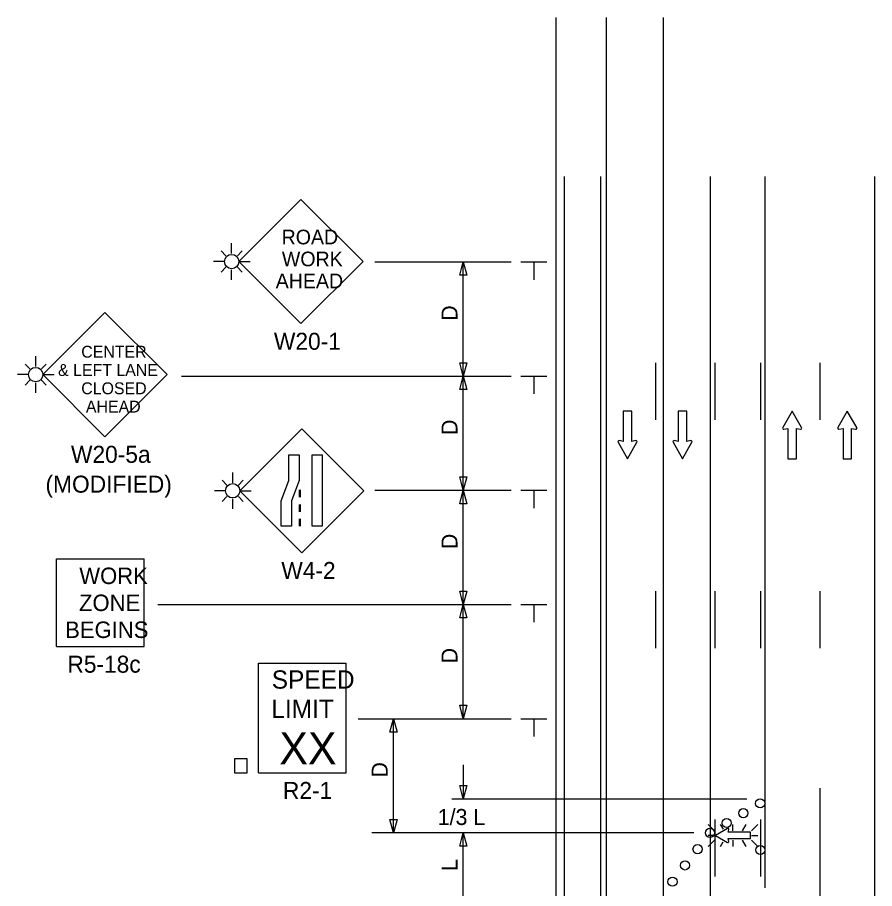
# Model space of a CAD drawing. Extents: x 16752 to 18475, y 7011 to 8262.
# Drawn here: x 16752.3 to 17127.7, y 7880.9 to 8262.3 of the extents above; entities that cross this region are included whole.
import ezdxf

# ---------------------------------------------------------------- set-up
doc = ezdxf.new("R2010")
doc.units = 0
for name, color, linetype in [('ALI_LEGAL_EX', 7, 'Continuous'), ('MT_SCRATCH_LEVEL_E', 7, 'Continuous'), ('PAVT_EDGE_EX', 7, 'Continuous'), ('TRAFFIC_SIGNS_PR', 7, 'Continuous'), ('TYPICAL_TEXT_DIMEN_PR', 7, 'Continuous')]:
    doc.layers.add(name, color=color, linetype=linetype)

msp = doc.modelspace()

# ---------------------------------------------------------------- linework, layer by layer
at = {"layer": 'ALI_LEGAL_EX'}
for points in [[(17031.71, 8111.16), (17031.71, 8086.16)], [(17031.71, 8111.16), (17031.71, 8086.16)], [(17057.71, 8111.16), (17057.71, 8086.16)], [(17057.71, 8111.16), (17057.71, 8086.16)], [(17077.71, 8111.16), (17077.71, 8086.16)], [(17077.71, 8111.16), (17077.71, 8086.16)], [(17103.71, 8111.16), (17103.71, 8086.16)], [(17103.71, 8111.16), (17103.71, 8086.16)], [(17031.71, 8011.16), (17031.71, 7986.16)], [(17031.71, 8011.16), (17031.71, 7986.16)], [(17057.71, 8011.16), (17057.71, 7986.16)], [(17057.71, 8011.16), (17057.71, 7986.16)], [(17077.71, 8011.16), (17077.71, 7986.16)], [(17077.71, 8011.16), (17077.71, 7986.16)], [(17103.71, 8011.16), (17103.71, 7986.16)], [(17103.71, 8011.16), (17103.71, 7986.16)], [(17057.71, 7911.16), (17057.71, 7886.16)], [(17057.71, 7911.16), (17057.71, 7886.16)], [(17077.71, 7911.16), (17077.71, 7886.16)], [(17077.71, 7911.16), (17077.71, 7886.16)], [(17103.71, 7911.16), (17103.71, 7886.16)]]:
    msp.add_lwpolyline(points, dxfattribs=at)
at = {"layer": 'MT_SCRATCH_LEVEL_E'}
for p, q in [((17021.38, 8089.95), (17017.64, 8089.95)), ((17017.64, 8089.95), (17017.64, 8076.7)), ((17021.38, 8089.95), (17017.64, 8089.95)), ((17017.64, 8089.95), (17017.64, 8076.7)), ((17021.38, 8089.95), (17017.64, 8089.95)), ((17017.64, 8089.95), (17017.64, 8076.7)), ((17021.38, 8089.95), (17017.64, 8089.95)), ((17017.64, 8089.95), (17017.64, 8076.7)), ((17021.38, 8076.7), (17021.38, 8089.95)), ((17021.38, 8076.7), (17021.38, 8089.95)), ((17021.38, 8076.7), (17021.38, 8089.95)), ((17021.38, 8076.7), (17021.38, 8089.95)), ((17045.45, 8089.95), (17041.71, 8089.95)), ((17041.71, 8089.95), (17041.71, 8076.7)), ((17045.45, 8089.95), (17041.71, 8089.95)), ((17041.71, 8089.95), (17041.71, 8076.7)), ((17045.45, 8089.95), (17041.71, 8089.95)), ((17041.71, 8089.95), (17041.71, 8076.7)), ((17045.45, 8089.95), (17041.71, 8089.95)), ((17041.71, 8089.95), (17041.71, 8076.7)), ((17045.45, 8076.7), (17045.45, 8089.95)), ((17045.45, 8076.7), (17045.45, 8089.95)), ((17045.45, 8076.7), (17045.45, 8089.95)), ((17045.45, 8076.7), (17045.45, 8089.95)), ((17091.58, 8089.95), (17087.47, 8082.71)), ((17091.58, 8089.95), (17087.47, 8082.71)), ((17095.73, 8082.71), (17091.58, 8089.95)), ((17095.73, 8082.71), (17091.58, 8089.95)), ((17115.75, 8089.95), (17111.64, 8082.71)), ((17115.75, 8089.95), (17111.64, 8082.71)), ((17119.9, 8082.71), (17115.75, 8089.95)), ((17119.9, 8082.71), (17115.75, 8089.95)), ((17087.95, 8082.03), (17089.73, 8082.34)), ((17087.95, 8082.03), (17089.73, 8082.34)), ((17089.73, 8082.34), (17089.73, 8069.09)), ((17089.73, 8082.34), (17089.73, 8069.09)), ((17093.47, 8069.09), (17093.47, 8082.34)), ((17093.47, 8082.34), (17095.25, 8082.03)), ((17093.47, 8069.09), (17093.47, 8082.34)), ((17093.47, 8082.34), (17095.25, 8082.03)), ((17112.12, 8082.03), (17113.9, 8082.34)), ((17112.12, 8082.03), (17113.9, 8082.34)), ((17113.9, 8082.34), (17113.9, 8069.09)), ((17113.9, 8082.34), (17113.9, 8069.09)), ((17117.64, 8069.09), (17117.64, 8082.34)), ((17117.64, 8082.34), (17119.42, 8082.03)), ((17117.64, 8069.09), (17117.64, 8082.34)), ((17117.64, 8082.34), (17119.42, 8082.03)), ((17015.38, 8076.33), (17019.53, 8069.09)), ((17015.38, 8076.33), (17019.53, 8069.09)), ((17015.38, 8076.33), (17019.53, 8069.09)), ((17015.38, 8076.33), (17019.53, 8069.09)), ((17017.64, 8076.7), (17015.86, 8077.01)), ((17017.64, 8076.7), (17015.86, 8077.01)), ((17017.64, 8076.7), (17015.86, 8077.01)), ((17017.64, 8076.7), (17015.86, 8077.01)), ((17019.53, 8069.09), (17023.64, 8076.33)), ((17019.53, 8069.09), (17023.64, 8076.33)), ((17019.53, 8069.09), (17023.64, 8076.33)), ((17019.53, 8069.09), (17023.64, 8076.33)), ((17023.16, 8077.01), (17021.38, 8076.7)), ((17023.16, 8077.01), (17021.38, 8076.7)), ((17023.16, 8077.01), (17021.38, 8076.7)), ((17023.16, 8077.01), (17021.38, 8076.7)), ((17039.45, 8076.33), (17043.6, 8069.09)), ((17039.45, 8076.33), (17043.6, 8069.09)), ((17039.45, 8076.33), (17043.6, 8069.09)), ((17039.45, 8076.33), (17043.6, 8069.09)), ((17041.71, 8076.7), (17039.93, 8077.01)), ((17041.71, 8076.7), (17039.93, 8077.01)), ((17041.71, 8076.7), (17039.93, 8077.01)), ((17041.71, 8076.7), (17039.93, 8077.01)), ((17043.6, 8069.09), (17047.71, 8076.33)), ((17043.6, 8069.09), (17047.71, 8076.33)), ((17043.6, 8069.09), (17047.71, 8076.33)), ((17043.6, 8069.09), (17047.71, 8076.33)), ((17047.23, 8077.01), (17045.45, 8076.7)), ((17047.23, 8077.01), (17045.45, 8076.7)), ((17047.23, 8077.01), (17045.45, 8076.7)), ((17047.23, 8077.01), (17045.45, 8076.7)), ((17089.73, 8069.09), (17093.47, 8069.09)), ((17089.73, 8069.09), (17093.47, 8069.09)), ((17113.9, 8069.09), (17117.64, 8069.09)), ((17113.9, 8069.09), (17117.64, 8069.09))]:
    msp.add_line(p, q, dxfattribs=at)
for centre, start, end in [((17087.88, 8082.49), 150.4248, 279.9638), ((17087.88, 8082.49), 150.4248, 279.9638), ((17095.32, 8082.49), 260.0362, 29.7731), ((17095.32, 8082.49), 260.0362, 29.7731), ((17112.05, 8082.49), 150.4248, 279.9638), ((17112.05, 8082.49), 150.4248, 279.9638), ((17119.49, 8082.49), 260.0362, 29.7731), ((17119.49, 8082.49), 260.0362, 29.7731), ((17015.79, 8076.55), 80.0362, 209.7731), ((17015.79, 8076.55), 80.0362, 209.7731), ((17015.79, 8076.55), 80.0362, 209.7731), ((17015.79, 8076.55), 80.0362, 209.7731), ((17023.23, 8076.55), 330.4248, 99.9638), ((17023.23, 8076.55), 330.4248, 99.9638), ((17023.23, 8076.55), 330.4248, 99.9638), ((17023.23, 8076.55), 330.4248, 99.9638), ((17039.86, 8076.55), 80.0362, 209.7731), ((17039.86, 8076.55), 80.0362, 209.7731), ((17039.86, 8076.55), 80.0362, 209.7731), ((17039.86, 8076.55), 80.0362, 209.7731), ((17047.3, 8076.55), 330.4248, 99.9638), ((17047.3, 8076.55), 330.4248, 99.9638), ((17047.3, 8076.55), 330.4248, 99.9638), ((17047.3, 8076.55), 330.4248, 99.9638)]:
    msp.add_arc(centre, 0.463, start, end, dxfattribs=at)
at = {"layer": 'PAVT_EDGE_EX'}
for p, q in [((16988.15, 8262.34), (16988.15, 7433.15)), ((17010.15, 8262.34), (17010.15, 7433.15)), ((17035.15, 8262.34), (17035.15, 7433.15)), ((16991.71, 8192.65), (16991.71, 7386.98)), ((17007.71, 8192.65), (17007.71, 7386.98)), ((17055.71, 8192.65), (17055.71, 7852.65)), ((17055.71, 8192.65), (17055.71, 7851.93)), ((17079.71, 8192.65), (17079.71, 7881.16)), ((17079.71, 8192.65), (17079.71, 7882.21)), ((17127.71, 8192.65), (17127.71, 7386.98)), ((17103.71, 7924.78), (17103.71, 7869.32))]:
    msp.add_line(p, q, dxfattribs=at)
at = {"layer": 'TRAFFIC_SIGNS_PR'}
for p, q in [((16876.5, 8182.62), (16849.32, 8155.44)), ((16903.69, 8155.44), (16876.5, 8182.62)), ((16846.16, 8158.99), (16846.16, 8163.49)), ((16843.65, 8157.95), (16841.54, 8160.06)), ((16848.68, 8157.95), (16850.78, 8160.06)), ((16843.01, 8155.44), (16838.17, 8155.44)), ((16843.65, 8152.92), (16841.54, 8150.81)), ((16846.16, 8147.47), (16846.16, 8151.88)), ((16848.68, 8152.92), (16850.78, 8150.82)), ((16849.32, 8155.44), (16876.5, 8128.25)), ((16849.32, 8155.44), (16854.2, 8155.44)), ((16876.5, 8128.25), (16903.69, 8155.44)), ((16790.67, 8133.12), (16763.48, 8105.94)), ((16817.85, 8105.94), (16790.67, 8133.12)), ((16760.33, 8109.49), (16760.33, 8113.99)), ((16757.81, 8108.45), (16755.71, 8110.56)), ((16762.84, 8108.45), (16764.95, 8110.56)), ((16757.17, 8105.94), (16752.33, 8105.94)), ((16757.81, 8103.43), (16755.71, 8101.32)), ((16760.33, 8097.97), (16760.33, 8102.38)), ((16762.84, 8103.43), (16764.95, 8101.32)), ((16763.48, 8105.94), (16790.67, 8078.75)), ((16763.48, 8105.94), (16768.36, 8105.94)), ((16763.48, 8105.94), (16790.67, 8078.75)), ((16790.67, 8078.75), (16817.85, 8105.94)), ((16876.95, 8082.17), (16849.8, 8055.02)), ((16904.1, 8055.02), (16876.95, 8082.17)), ((16846.61, 8058.61), (16846.61, 8063.11)), ((16844.1, 8057.57), (16841.99, 8059.68)), ((16849.12, 8057.57), (16851.23, 8059.68)), ((16843.46, 8055.06), (16838.62, 8055.06)), ((16849.76, 8055.06), (16854.65, 8055.06)), ((16849.8, 8055.02), (16876.95, 8027.87)), ((16875.7, 8055.51), (16875.7, 8052.31)), ((16876.1, 8055.51), (16876.1, 8052.31)), ((16876.95, 8027.87), (16904.1, 8055.02)), ((16844.1, 8052.54), (16841.99, 8050.43)), ((16846.61, 8047.09), (16846.61, 8051.5)), ((16849.12, 8052.54), (16851.23, 8050.44)), ((16875.7, 8049.11), (16875.7, 8045.91)), ((16876.1, 8049.11), (16876.1, 8045.91)), ((16875.7, 8042.71), (16875.7, 8039.51)), ((16876.1, 8042.71), (16876.1, 8039.51)), ((16769.43, 7986.85), (16769.43, 8025.25)), ((16769.43, 8025.25), (16807.83, 8025.25)), ((16807.83, 7986.85), (16807.83, 8025.25)), ((16769.43, 7986.85), (16807.83, 7986.85)), ((16857.94, 7979.56), (16896.34, 7979.56)), ((16857.94, 7931.56), (16857.94, 7979.56)), ((16896.34, 7931.56), (16896.34, 7979.56)), ((16857.94, 7931.56), (16896.34, 7931.56)), ((17054.8, 7909), (17057.62, 7906.18)), ((17061.52, 7906.82), (17060.26, 7909)), ((17065.7, 7906.18), (17065.7, 7909)), ((17069.83, 7906.18), (17071.46, 7909)), ((17073.78, 7906.18), (17076.61, 7909)), ((17057.62, 7904.15), (17054.8, 7904.15)), ((17073.78, 7904.15), (17076.61, 7904.15)), ((17054.8, 7899.3), (17057.62, 7902.12)), ((17060.23, 7899.3), (17061.44, 7901.39)), ((17065.7, 7902.12), (17065.7, 7899.3)), ((17071.49, 7899.3), (17069.86, 7902.12)), ((17073.78, 7902.12), (17076.61, 7899.3))]:
    msp.add_line(p, q, dxfattribs=at)
for points in [[(16875.7, 8070.76), (16875.7, 8059.58), (16872.36, 8050.69), (16872.36, 8039.51), (16867.87, 8039.51), (16867.87, 8050.69), (16871.21, 8059.58), (16871.21, 8070.76)], [(16885.84, 8070.76), (16885.84, 8039.51), (16881.35, 8039.51), (16881.35, 8070.76)], [(16847.33, 7931.56), (16852.92, 7931.56), (16852.92, 7937.73), (16847.33, 7937.73)]]:
    msp.add_lwpolyline(points, close=True, dxfattribs=at)
for points in [[(17063.37, 7907.16), (17058.06, 7904.15), (17063.37, 7901.11)], [(17063.87, 7901.47), (17063.64, 7902.76), (17073.37, 7902.76), (17073.37, 7905.51), (17063.64, 7905.51), (17063.88, 7906.81)]]:
    msp.add_lwpolyline(points, dxfattribs=at)
for centre, radius in [((16846.16, 8155.44), 3.15), ((16760.33, 8105.94), 3.15), ((16846.61, 8055.06), 3.15), ((17077.6, 7918.19), 2), ((17070.27, 7913.88), 2), ((17062.94, 7909.57), 2), ((17055.61, 7905.27), 2), ((17050.19, 7898.13), 2), ((17077.65, 7897.79), 2), ((17044.7, 7891.01), 2), ((17039.21, 7883.88), 2)]:
    msp.add_circle(centre, radius, dxfattribs=at)
for centre, start, end in [((17063.54, 7906.87), 350.7308, 118.8916), ((17063.54, 7901.41), 241.4833, 9.9593)]:
    msp.add_arc(centre, 0.341, start, end, dxfattribs=at)
at = {"layer": 'TYPICAL_TEXT_DIMEN_PR'}
for p, q in [((16908.85, 8155.27), (16968.61, 8155.27)), ((16946.04, 8149.41), (16947.61, 8155.27)), ((16946.04, 8149.41), (16947.61, 8155.27)), ((16947.61, 8155.27), (16949.18, 8149.41)), ((16947.61, 8155.27), (16949.18, 8149.41)), ((16947.61, 8105.27), (16947.61, 8155.27)), ((16972.86, 8155.27), (16984.11, 8155.27)), ((16972.86, 8155.27), (16984.11, 8155.27)), ((16978.49, 8155.27), (16978.49, 8147.49)), ((16978.49, 8155.27), (16978.49, 8147.49)), ((16947.61, 8149.41), (16946.04, 8149.41)), ((16947.61, 8149.41), (16946.04, 8149.41)), ((16949.18, 8149.41), (16947.61, 8149.41)), ((16949.18, 8149.41), (16947.61, 8149.41)), ((16947.61, 8105.27), (16946.04, 8111.13)), ((16946.04, 8111.13), (16947.61, 8111.13)), ((16947.61, 8105.27), (16946.04, 8111.13)), ((16946.04, 8111.13), (16947.61, 8111.13)), ((16947.61, 8111.13), (16949.18, 8111.13)), ((16949.18, 8111.13), (16947.61, 8105.27)), ((16947.61, 8111.13), (16949.18, 8111.13)), ((16949.18, 8111.13), (16947.61, 8105.27)), ((16824.2, 8105.27), (16968.61, 8105.27)), ((16946.04, 8099.41), (16947.61, 8105.27)), ((16946.04, 8099.41), (16947.61, 8105.27)), ((16947.61, 8105.27), (16949.18, 8099.41)), ((16947.61, 8055.27), (16947.61, 8105.27)), ((16947.61, 8105.27), (16949.18, 8099.41)), ((16947.61, 8055.27), (16947.61, 8105.27)), ((16972.86, 8105.27), (16984.11, 8105.27)), ((16978.49, 8105.27), (16978.49, 8097.49)), ((16947.61, 8099.41), (16946.04, 8099.41)), ((16947.61, 8099.41), (16946.04, 8099.41)), ((16949.18, 8099.41), (16947.61, 8099.41)), ((16949.18, 8099.41), (16947.61, 8099.41)), ((16947.61, 8055.27), (16946.04, 8061.13)), ((16946.04, 8061.13), (16947.61, 8061.13)), ((16947.61, 8055.27), (16946.04, 8061.13)), ((16946.04, 8061.13), (16947.61, 8061.13)), ((16947.61, 8061.13), (16949.18, 8061.13)), ((16949.18, 8061.13), (16947.61, 8055.27)), ((16947.61, 8061.13), (16949.18, 8061.13)), ((16949.18, 8061.13), (16947.61, 8055.27)), ((16908.85, 8055.27), (16968.61, 8055.27)), ((16946.04, 8049.41), (16947.61, 8055.27)), ((16946.04, 8049.41), (16947.61, 8055.27)), ((16947.61, 8055.27), (16949.18, 8049.41)), ((16947.61, 8055.27), (16949.18, 8049.41)), ((16947.61, 8005.27), (16947.61, 8055.27)), ((16972.86, 8055.27), (16984.11, 8055.27)), ((16972.86, 8055.27), (16984.11, 8055.27)), ((16978.49, 8055.27), (16978.49, 8047.49)), ((16978.49, 8055.27), (16978.49, 8047.49)), ((16947.61, 8049.41), (16946.04, 8049.41)), ((16947.61, 8049.41), (16946.04, 8049.41)), ((16949.18, 8049.41), (16947.61, 8049.41)), ((16949.18, 8049.41), (16947.61, 8049.41)), ((16947.61, 8005.27), (16946.04, 8011.13)), ((16946.04, 8011.13), (16947.61, 8011.13)), ((16947.61, 8005.27), (16946.04, 8011.13)), ((16946.04, 8011.13), (16947.61, 8011.13)), ((16947.61, 8011.13), (16949.18, 8011.13)), ((16949.18, 8011.13), (16947.61, 8005.27)), ((16947.61, 8011.13), (16949.18, 8011.13)), ((16949.18, 8011.13), (16947.61, 8005.27)), ((16813.85, 8005.27), (16968.61, 8005.27)), ((16946.04, 7999.41), (16947.61, 8005.27)), ((16946.04, 7999.41), (16947.61, 8005.27)), ((16947.61, 8005.27), (16949.18, 7999.41)), ((16947.61, 7955.27), (16947.61, 8005.27)), ((16947.61, 8005.27), (16949.18, 7999.41)), ((16947.61, 7955.27), (16947.61, 8005.27)), ((16972.86, 8005.27), (16984.11, 8005.27)), ((16978.49, 8005.27), (16978.49, 7997.49)), ((16947.61, 7999.41), (16946.04, 7999.41)), ((16947.61, 7999.41), (16946.04, 7999.41)), ((16949.18, 7999.41), (16947.61, 7999.41)), ((16949.18, 7999.41), (16947.61, 7999.41)), ((16947.61, 7955.27), (16946.04, 7961.13)), ((16946.04, 7961.13), (16947.61, 7961.13)), ((16947.61, 7955.27), (16946.04, 7961.13)), ((16946.04, 7961.13), (16947.61, 7961.13)), ((16947.61, 7961.13), (16949.18, 7961.13)), ((16949.18, 7961.13), (16947.61, 7955.27)), ((16947.61, 7961.13), (16949.18, 7961.13)), ((16949.18, 7961.13), (16947.61, 7955.27)), ((16901.49, 7955.27), (16968.61, 7955.27)), ((16915.47, 7949.41), (16917.04, 7955.27)), ((16917.04, 7955.27), (16918.61, 7949.41)), ((16917.04, 7905.27), (16917.04, 7955.27)), ((16972.86, 7955.27), (16984.11, 7955.27)), ((16978.49, 7955.27), (16978.49, 7947.49)), ((16917.04, 7949.41), (16915.47, 7949.41)), ((16918.61, 7949.41), (16917.04, 7949.41)), ((16947.61, 7935.11), (16947.61, 7920.19)), ((16947.61, 7920.19), (16946.04, 7926.06)), ((16946.04, 7926.06), (16947.61, 7926.06)), ((16947.61, 7920.19), (16946.04, 7926.06)), ((16946.04, 7926.06), (16947.61, 7926.06)), ((16947.61, 7926.06), (16949.18, 7926.06)), ((16949.18, 7926.06), (16947.61, 7920.19)), ((16947.61, 7926.06), (16949.18, 7926.06)), ((16949.18, 7926.06), (16947.61, 7920.19)), ((16942.61, 7920.19), (17071.75, 7920.19)), ((16917.04, 7905.27), (16915.47, 7911.13)), ((16915.47, 7911.13), (16917.04, 7911.13)), ((16917.04, 7911.13), (16918.61, 7911.13)), ((16918.61, 7911.13), (16917.04, 7905.27)), ((17048.53, 7905.27), (16907.52, 7905.27)), ((17048.53, 7905.27), (16917.04, 7905.27)), ((16946.04, 7899.41), (16947.61, 7905.27)), ((16947.61, 7874.74), (16947.61, 7905.27)), ((16947.61, 7905.27), (16949.18, 7899.41)), ((16947.61, 7899.41), (16946.04, 7899.41)), ((16949.18, 7899.41), (16947.61, 7899.41))]:
    msp.add_line(p, q, dxfattribs=at)

# ---------------------------------------------------------------- texts
at = {"layer": 'TRAFFIC_SIGNS_PR'}
for s, height, p in [('ROAD', 6.408, (16868.03, 8162.98)), ('WORK', 6.408, (16868.14, 8153.37)), ('AHEAD', 6.408, (16865.45, 8143.76)), ('W20-1', 7.449, (16864.66, 8116.8)), ('CENTER', 5.206, (16780.29, 8113.35)), ('& LEFT LANE', 5.2065, (16770.14, 8105.34)), ('CLOSED', 5.206, (16780.29, 8097.33)), ('AHEAD', 5.206, (16782.32, 8089.32)), ('W20-5a', 7.449, (16775.79, 8067.3)), ('(MODIFIED)', 7.449, (16764.63, 8054.24)), ('W4-2', 7.44, (16867.91, 8016.43)), ('WORK', 7.217, (16779.43, 8014.22)), ('ZONE', 7.217, (16779.31, 8002.4)), ('BEGINS', 7.217, (16773.24, 7990.6)), ('R5-18c', 7.44, (16774.24, 7975.41)), ('SPEED', 8, (16863.71, 7968.42)), ('LIMIT', 8, (16863.55, 7955.62)), ('XX', 14.031, (16867.05, 7935.32)), ('R2-1', 7.44, (16868.62, 7920.12))]:
    msp.add_text(s, height=height, dxfattribs=at).set_placement(p)
at = {"layer": 'TYPICAL_TEXT_DIMEN_PR'}
for s, p in [('D', (16945.06, 8129.49)), ('D', (16945.06, 8129.49)), ('D', (16945.06, 8079.49)), ('D', (16945.06, 8079.49)), ('D', (16945.06, 8029.49)), ('D', (16945.06, 8029.49)), ('D', (16945.06, 7979.49)), ('D', (16945.06, 7979.49)), ('D', (16914.48, 7929.49)), ('L', (16945.06, 7888.6))]:
    msp.add_text(s, height=7, rotation=90, dxfattribs=at).set_placement(p)
msp.add_text('1/3 L', height=7, dxfattribs=at).set_placement((16936.4, 7908.72))
msp.add_text('1/3 L', height=7, dxfattribs=at).set_placement((16936.4, 7908.72))

doc.saveas('drawing.dxf')
